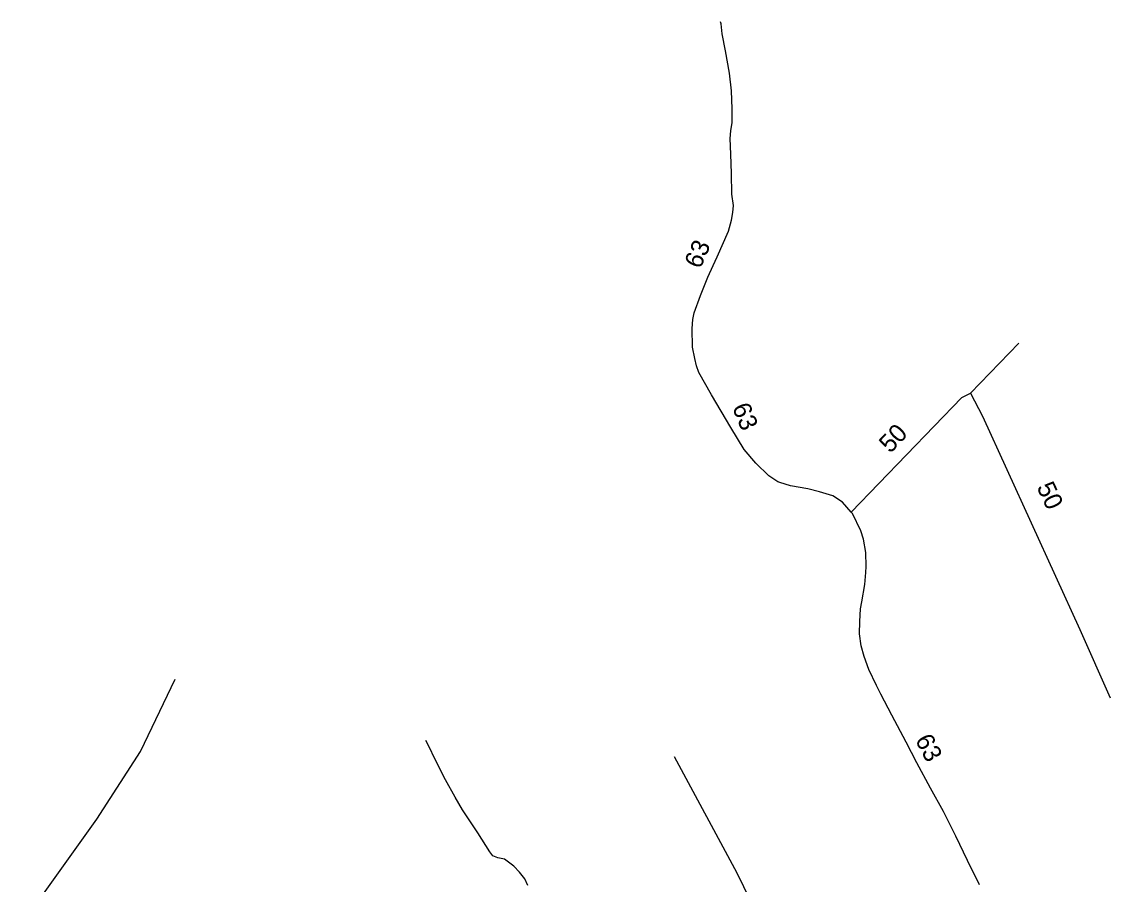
# Model space of a CAD drawing. Extents: x -444841 to -429545, y -1135312 to -1129851.
# Drawn here: x -442171.6 to -441689.3, y -1130232.9 to -1129850.9 of the extents above; entities that cross this region are included whole.
import ezdxf

# ---------------------------------------------------------------- set-up
doc = ezdxf.new("R2010")
doc.units = 0
for name, color, linetype in [('Vrstva 27', 7, 'Continuous'), ('Vrstva 30', 7, 'Continuous'), ('Vrstva 35', 7, 'Continuous'), ('Vrstva 38', 7, 'Continuous'), ('Vrstva 58', 7, 'Continuous')]:
    doc.layers.add(name, color=color, linetype=linetype)

msp = doc.modelspace()

# ---------------------------------------------------------------- linework, layer by layer
at = {"layer": 'Vrstva 27'}
for points in [[(-441873.33, -1130000), (-441874.46, -1129995), (-441874.56, -1129986.78), (-441874.3, -1129982.8), (-441873.59, -1129979.9), (-441870.9, -1129972.09), (-441867.64, -1129964), (-441865.26, -1129958.84), (-441863.47, -1129954.97), (-441858.5, -1129943.63), (-441857.14, -1129938.83), (-441856.49, -1129935.43), (-441856.29, -1129932.33), (-441856.95, -1129927.24), (-441857.17, -1129918.07), (-441857.34, -1129909.54), (-441857.77, -1129902.54), (-441857.35, -1129899.15), (-441856.82, -1129895.55), (-441856.8, -1129889.44), (-441857.09, -1129881.47), (-441858.03, -1129873.7), (-441859.77, -1129863.85), (-441861.23, -1129856.22), (-441861.75, -1129851.81), (-441861.96, -1129850.91)], [(-441747.14, -1130233.17), (-441752.52, -1130222.43), (-441757.71, -1130211.69), (-441763.23, -1130200.74), (-441768.88, -1130190.33), (-441774.91, -1130179.12), (-441779.74, -1130169.97), (-441786.02, -1130158.12), (-441790.97, -1130148.78), (-441792.84, -1130144.87), (-441796.25, -1130137.82), (-441798.39, -1130132.05), (-441799.69, -1130127.35), (-441800.35, -1130122.05), (-441800.28, -1130116.52), (-441799.98, -1130110.92), (-441799.31, -1130107.87), (-441797.98, -1130100.2), (-441797.62, -1130094.84), (-441797.44, -1130092.23), (-441797.54, -1130085.93), (-441798.59, -1130080.11), (-441799.76, -1130076.34), (-441803.5, -1130068.67), (-441804.13, -1130068.12), (-441807.87, -1130063.7), (-441812.27, -1130060.96), (-441818.18, -1130059.16), (-441823.25, -1130057.86), (-441830.93, -1130056.48), (-441835.74, -1130054.93), (-441836.52, -1130054.68), (-441840.56, -1130052.01), (-441846.3, -1130046.39), (-441851.48, -1130040.38), (-441857.42, -1130030.6), (-441865.94, -1130016.19), (-441871.52, -1130006.27), (-441872.58, -1130003.33), (-441873.33, -1130000)], [(-441947.32, -1130233.56), (-441948.66, -1130230.5), (-441951.06, -1130227.54), (-441953.51, -1130224.92), (-441957.72, -1130221.82), (-441960.6, -1130221.32), (-441962.87, -1130220.33), (-441964.16, -1130218.55), (-441969.52, -1130210.23), (-441976.29, -1130199.95), (-441979.52, -1130194.33), (-441983.87, -1130186.68), (-441987.98, -1130178.65), (-441991.69, -1130170.94), (-441992.59, -1130169.31)]]:
    msp.add_lwpolyline(points, dxfattribs=at)
at = {"layer": 'Vrstva 35'}
msp.add_line((-441751.23, -1130015.42), (-441729.8, -1129993.26), dxfattribs=at)
for points in [[(-441804.13, -1130068.12), (-441755.02, -1130017.31), (-441751.23, -1130015.42), (-441745.83, -1130025.62), (-441702.68, -1130120.08), (-441689.27, -1130150.4)], [(-441792.9, -1130354.63), (-441854.53, -1130228.08), (-441882.43, -1130176.46)]]:
    msp.add_lwpolyline(points, dxfattribs=at)
at = {"layer": 'Vrstva 58'}
msp.add_lwpolyline([(-442168.69, -1130285.83), (-442163.33, -1130276.21), (-442162, -1130272.56), (-442159.36, -1130266.71), (-442157.94, -1130260.51), (-442159.56, -1130259.6), (-442160.01, -1130259.2), (-442160.51, -1130260.25), (-442168.79, -1130255.9), (-442168.24, -1130255.5), (-442168.29, -1130255.21), (-442171.63, -1130253.27), (-442166.44, -1130243.47), (-442138.31, -1130204.19), (-442119.03, -1130174.17), (-442103.65, -1130142.05)], dxfattribs=at)

# ---------------------------------------------------------------- texts
at = {"layer": 'Vrstva 30'}
for rotation, p in [(66.3335, (-441871, -1129960.73)), (292.3508, (-441856.94, -1130021.67)), (297.8282, (-441775.91, -1130169))]:
    msp.add_text('63', height=8, rotation=rotation, dxfattribs=at).set_placement(p)
at = {"layer": 'Vrstva 38'}
for rotation, p in [(46.6872, (-441786.73, -1130042.37)), (295.2532, (-441722.03, -1130057.01))]:
    msp.add_text('50', height=8, rotation=rotation, dxfattribs=at).set_placement(p)

doc.saveas('drawing.dxf')
